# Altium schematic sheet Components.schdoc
size 200 x 65 mm
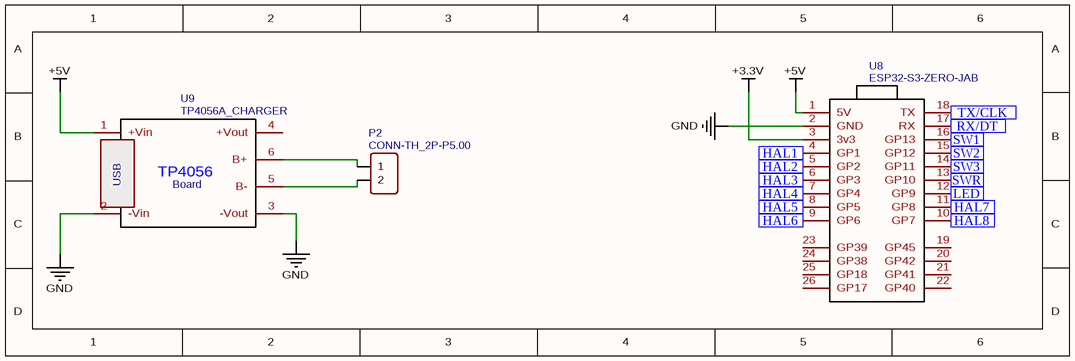
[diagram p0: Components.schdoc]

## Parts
P2  CONN-TH_2P-P5.00  [CONN-TH_2P-P5.00]
U8  ESP32-S3-ZERO-JAB  [ESP32-S3-ZERO JAB]
U9  TP4056A_CHARGER  [TP4056A_CHARGER_BOARD]

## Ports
HAL1 (in), HAL2 (in), HAL3 (in), HAL4 (in), HAL5 (in), HAL6 (in), HAL7 (in), HAL8 (in), LED (in), RX/DT (in), SW1 (in), SW2 (in), SW3 (in), SWR (in), TX/CLK (in)

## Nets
+3.3V: U8.3(3v3)
+5V: U8.1(5V) U9.1(+Vin)
GND: U8.2(GND) U9.2(-Vin) U9.3(-Vout)
HAL1: U8.4(GP1) ; port HAL1
HAL2: U8.5(GP2) ; port HAL2
HAL3: U8.6(GP3) ; port HAL3
HAL4: U8.7(GP4) ; port HAL4
HAL5: U8.8(GP5) ; port HAL5
HAL6: U8.9(GP6) ; port HAL6
HAL7: U8.11(GP8) ; port HAL7
HAL8: U8.10(GP7) ; port HAL8
LED: U8.12(GP9) ; port LED
RX/DT: U8.17(RX) ; port RX/DT
SW1: U8.16(GP13) ; port SW1
SW2: U8.15(GP12) ; port SW2
SW3: U8.14(GP11) ; port SW3
SWR: U8.13(GP10) ; port SWR
TX/CLK: U8.18(TX) ; port TX/CLK
NetP2_1: P2.1 U9.6(B+)
NetP2_2: P2.2 U9.5(B-)

Not connected (* = marked no-connect by the designer): U8 19(GP45) 20(GP42) 21(GP41) 22(GP40) 23(GP39) 24(GP38) 25(GP18) 26(GP17); U9 4(+Vout)

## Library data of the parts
P2 = CONN-TH_2P-P5.00: Contributor: LCEDA_Lib
U8 = ESP32-S3-ZERO-JAB: Contributor: samahosam
U9 = TP4056A_CHARGER: Contributor: lucianscripca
